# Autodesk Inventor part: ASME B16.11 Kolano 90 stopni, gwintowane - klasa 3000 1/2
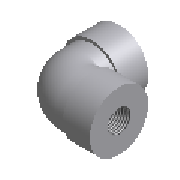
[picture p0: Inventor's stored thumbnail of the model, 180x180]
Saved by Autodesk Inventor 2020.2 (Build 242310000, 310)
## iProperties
Manager: www.cadconsulting.pl
Company: Fabian Stasiak CAD Consulting
Created: 2014-02
Part Number: ASME B16.11 Kolano 90 stopni, gwintowane - klasa 3000 1/2
Material: Stal
Description: Kolano 90º, kute, gwintowane - klasa 3000
Document SubType Name: Modeling
Standard: ASME B16.11
Designer: F.Stasiak
Standard Revision: 2005
Standards Organization: ANSI
Language: pl-PL
Size Designation: 1/2
Categories: <MemberInstance><Categories><Category DisplayName="Rury cienko- i grubościenne" InternalName="4347fa0f-2144-441d-94cd-e3e15c92b736" Mnemonic="TUBEANDPIPE"><Cate
Density: 1 g/cm^3
Appearance: Płyta
Catalog Web Link: www.expertbooks.pl
IsCustomPart: 0
NAME: PIPING: ASME B16.11 90 Deg Elbow Threaded - Class 3000
DATA: <meta><inlinegroups number="0" deflen="0"></inlinegroups><connections number="2"></connections><angles><a>1.57079632679489</a></angles></meta>
Author: F.Stasiak
Subject: Zbiór ćwiczeń. Autodesk Inventor 2020. Kurs Professional
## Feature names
1. Sweep1
2. Revolve1
3. Revolve2
4. Revolve3
5. Revolve4
6. Sweep2
## Parameters: MD = 18.32077 mm, A = 33.274 mm, L2 = 13.55598 mm, G = 4.0894 mm, d0 = 18.32077 mm, d1 = 38.1 mm, d2 = 0.3124 mm, d3 = 0.3124 mm, d4 = 18.32077 mm, d5 = 38.1 mm, H = 38.1 mm, d6 = 13.55598 mm, d7 = 26.1112 mm, d8 = 13.55598 mm, d9 = 26.1112 mm, d10 = 0, d11 = 9.9822 mm, d12 = 9.9822 mm, d13 = 17.145 mm, d14 = 0, d101 = 90 deg, d102 = 90 deg, d105 = 25.4 mm, d106 = 0, d107 = 25.4 mm, d108 = 0, d15 = 33.274 mm, d16 = 16.637 mm, d17 = 33.274 mm, d18 = 16.637 mm, d19 = 34.29 mm, d20 = 34.29 mm, d21 = 9.9822 mm, d116 = 90 deg, d117 = 90 deg, d22 = 13.05564 mm, d23 = 0, d122 = 0, d123 = 0, Size_Designation = 5 mm
